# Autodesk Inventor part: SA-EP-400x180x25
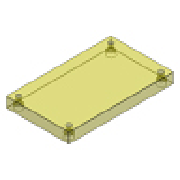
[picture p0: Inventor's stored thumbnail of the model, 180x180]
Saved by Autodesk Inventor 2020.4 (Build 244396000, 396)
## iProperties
Created: 2019-01
Part Number: SA-EP-400x180x25
Material: S 55 C
Description: Ejector Plate
Document SubType Name: Modeling
Designer: mel
Standard Revision: 1
Manufacturer: FUTABA
Language: fr-FR
Size Designation: 400x180x25
Categories: <MemberInstance><Categories><Category DisplayName="Moule" InternalName="349578f2-f4d4-4954-8c09-8e99297a61c0" Mnemonic="MOLD"><Category DisplayName="Plaque de m
Density: 7.85 g/cm^3
Appearance: Clear - Yellow
IsCustomPart: 1
Author: mel
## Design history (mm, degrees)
sketch "Sketch1"
  geometry: L1 (-90, 200)-(90, 200); L2 (90, 200)-(90, -200); L3 (90, -200)-(-90, -200); L4 (-90, -200)-(-90, 200); 4 further points
  constraints: 8 end point, 2 midpoint, 2 parallel, 1 horizontal, 1 horizontal alignment, 1 perpendicular, 1 vertical alignment
  dimensions: "d74" = 78 horizontal distance of point (0, 0) point (-78, 188) (= 0.5 x S2_W); "d75" = 188 vertical distance of point (0, 0) point (-78, 188) (= 0.5 x S2_L); "d92" = 180 distance between parallel lines of L2 L4 (= W_); "d93" = 400 distance between parallel lines of L3 L1 (= L)
extrude "Extrusion1" new body sketch "Sketch1" distance "d20" = 25 (= H_); taper "d30" = 0 deg
hole "Hole1" sketch "Sketch1" diameter "d76" = 11 (= S2_d1); stored, may be unused: countersink angle "d80" = 90 deg, drill point angle "d82" = 0 deg; dims "d77" = 6, "d78" = 18 (= S2_d2), "d79" = 11 (= S2_k), "d81" = 25 (= H_)
pattern_linear "Rectangular Pattern1" dims "d85" = 376 (computed from S2_L, Nl), "d88" = 156 (computed from S2_W, Nw)
chamfer "Chamfer1" distance "d89" = 0.5; stored, may be unused: second distance "d90" = 2, angle "d91" = 45 deg
body "Solid1"
other parameters: "L" = 400 [user parameter; used in 1 equation term], "W_" = 180 [user parameter; used in 1 equation term], "H_" = 25 [user parameter; used in 2 equation terms], "S2_W" = 156 [user parameter; used in 2 equation terms], "S2_d1" = 11 [user parameter; used in 1 equation term], "S2_d2" = 18 [user parameter; used in 1 equation term], "S2_k" = 11 [user parameter; used in 1 equation term], "S2_L" = 376 [user parameter; used in 2 equation terms]
